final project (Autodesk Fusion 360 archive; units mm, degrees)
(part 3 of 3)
sketch "Sketch40" plane through (0, 0, 61) normal (0, 0, -1) x axis (1, 0, 0)
  line L1 (-2.7532, -2.8573) -> (-0.5532, -2.8573)
  line L2 (-2.7532, -1.0573) -> (-2.7532, -2.8573)
  line L3 (-0.5532, -1.0573) -> (-2.7532, -1.0573)
  line L4 (-0.5532, -2.8573) -> (-0.5532, -1.0573)
  line L5 (-2.7532, 0.4427) -> (-0.5532, 0.4427)
  line L6 (-2.7532, 2.1427) -> (-2.7532, 0.4427)
  line L7 (-0.5532, 2.1427) -> (-2.7532, 2.1427)
  line L8 (-0.5532, 0.4427) -> (-0.5532, 2.1427)
  line L9 (-2.7532, -6.1573) -> (-0.5532, -6.1573)
  line L10 (-2.7532, -4.2573) -> (-2.7532, -6.1573)
  line L11 (-0.5532, -4.2573) -> (-2.7532, -4.2573)
  line L12 (-0.5532, -6.1573) -> (-0.5532, -4.2573)
  line L13 (2.1468, -6.9573) -> (-4.8532, -6.9573)
  line L14 (2.1468, 3.5427) -> (2.1468, -6.9573)
  line L15 (-4.8532, 3.5427) -> (2.1468, 3.5427)
  line L16 (-4.8532, -6.9573) -> (-4.8532, 3.5427)
  circle C1 centre (1, -3) radius 1
  circle C2 centre (-3.6986, -0.074) radius 1
  dimension "d376" diameter C1 = 2
  dimension "d377" diameter C2 = 2
offset_faces "OffsetFaces3" distance -0.3
position "Position24"
work_plane "WorkPlane2" AlongDistance -10
sketch "Sketch46" plane through (0, -46, 0) normal (0, -1, 0) x axis (-1, 0, 0)
  circle C1 centre (-5, 0) radius 2.87
  circle C2 centre (5, 0) radius 2.87
  circle C3 centre (5, 0) radius 3.6
  circle C4 centre (-5, 0) radius 3.6
  concentric C2 C3
  concentric C1 C4
  dimension "d428" diameter C1 = 5.74
  dimension "d429" diameter C2 = 5.74
extrude "Extrude64" add sketch "Sketch46" against normal blind 3
fillet "Fillet21" radius 6
fillet "Fillet22" radius 1.75
extrude "Extrude65" cut of existing geometry blind -2.3
delete_face "DeleteFace3"
delete_face "DeleteFace4"
delete_face "DeleteFace5"
delete_face "DeleteFace6"
chamfer "Chamfer10" distance 1
fillet "Fillet23" radius 1
extrude "Extrude66" cut of existing geometry blind -0.4
extrude "Extrude2" add sketch "Sketch40" profile of C1 C2 along normal blind 2
move "Move2"
combine "Combine12"
move "Move3"
move "Move4"
move "Move1"
move "Move2"
split "Split2"
fillet "Fillet11" radius 2
sketch "Sketch39" plane through (-4.8984, -6.1813, -26.5444) normal (0, 1, 0) x axis (-1, 0, 0)
  curve K1 (9.9684, 4.6149) -> (-9.6449, 8.3119)
  curve K2 (-9.6449, -8.3119) -> (9.9684, -4.6149)
  arc A1 centre (0, 0) radius 12.7324 clockwise from (-9.6449, -8.3119) to (-9.6449, 8.3119)
  arc A2 centre (0, 0) radius 10.9848 clockwise from (9.9684, 4.6149) to (9.9684, -4.6149)
  circle C1 centre (0, 0) radius 3.5
  point P1 (0, 0)
  point P7 (0, 0)
  coincident P1 P7
  dimension "d322" diameter C1 = 7
extrude "Extrude8" cut sketch "Sketch39" profile of C1 against normal blind 9
combine "Combine7"
align "Align1"
fillet "Fillet12" radius 5.75
extrude "Extrude48" sketch "Sketch33" profile of L37 L38 L39 L40 L69 L71 blind -35 from offset 0.5
extrude "Extrude3" sketch "Sketch33" profile of L22 L23 L24 L26 L29 L30 L32 L31 L33 L34 L35 L36 L41 to an object from offset 1
sketch "Sketch1" plane through (0, -41, 0) normal (0, 1, 0) x axis (-1, 0, 0)
  line L1 (21.3009, -9.8876) -> (21.3009, -11.0576)
  line L2 (18.8009, -9.8876) -> (21.3009, -9.8876)
  line L3 (-18.8009, -9.8876) -> (18.8009, -9.8876)
  line L4 (-21.3009, -9.8876) -> (-18.8009, -9.8876)
  line L5 (-21.3009, -9.8876) -> (-21.3009, -11.0576)
  line L6 (-21.3009, -11.0576) -> (-18.8009, -11.0576)
  line L7 (-18.8009, -11.0576) -> (18.8009, -11.0576)
  line L8 (18.8009, -11.0576) -> (21.3009, -11.0576)
  line L9 (8.5, -15.4444) -> (-8.5, -15.4444)
  line L10 (8.5, -22.4444) -> (8.5, -15.4444)
  line L11 (-8.5, -22.4444) -> (8.5, -22.4444)
  line L12 (-8.5, -15.4444) -> (-8.5, -22.4444)
  line L13 (27, 0) -> (25.3, 0)
  line L14 (-25.2982, -0.3) -> (-26.9983, -0.3)
  arc A1 centre (0, 0) radius 25.3 clockwise from (-25.2982, -0.3) to (25.3, 0)
  arc A2 centre (0, 0) radius 24 clockwise from (-23.5661, -4.543) to (23.5661, -4.543)
  arc A3 centre (0, 0) radius 24 clockwise from (23.5661, -4.543) to (-23.5073, -4.838)
  arc A4 centre (0, 0) radius 27 clockwise from (-26.9983, -0.3) to (27, 0)
  point P22 (-8.5, -22.4444)
  point P21 (8.5, -22.4444)
  point P19 (-8.5, -15.4444)
  horizontal L9
  vertical L10
  horizontal L11
  vertical L12
  coincident A3 P22
  coincident A3 P21
  dimension "d333" distance P21 P22 = 17
  dimension "d334" distance P19 P22 = 7
extrude "Extrude1" new body sketch "Sketch1" profile of L9 L10 L11 L12 blind 37 from offset 0.5
combine "Combine5"
offset_faces "OffsetFaces2" distance -0.3
sketch "Sketch41" plane through (-0.0452, -38.1813, 0) normal (0, 1, 0) x axis (-1, 0, 0)
  line L1 (-6.6018, -25.2535) -> (-13, -25.2535)
  line L2 (-6.6018, -28.2535) -> (-6.6018, -25.2535)
  line L3 (-13, -28.2535) -> (-6.6018, -28.2535)
  line L4 (-13, -25.2535) -> (-13, -28.2535)
  line L5 (-6.6018, -28.2535) -> (-13, -25.2535)
  line L6 (-13, -28.2535) -> (-6.6018, -25.2535)
  circle C1 centre (-15.1468, -26.5444) radius 5.35
  point P7 (-9.8009, -26.7535)
  horizontal L1
  perpendicular L1 L2
  parallel L1 L3
  parallel L2 L4
  coincident L5 P7
  coincident L6 P7
  coincident C1 P7
  dimension "d386" distance L1 L3 = 3
extrude "Extrude15" cut sketch "Sketch41" profile of C1 L1 L2 L3 L4 along normal blind 3
sketch "Sketch42" plane through (-0.0452, -38.1813, 0) normal (0, 1, 0) x axis (-1, 0, 0)
  line L1 (17.2217, -25) -> (24, -25)
  line L2 (17.2217, -28.4977) -> (17.2217, -25)
  line L3 (24, -28.4977) -> (17.2217, -28.4977)
  line L4 (24, -25) -> (24, -28.4977)
  line L5 (17.2217, -28.4977) -> (24, -25)
  line L6 (24, -28.4977) -> (17.2217, -25)
  circle C1 centre (24.8532, -26.5444) radius 5.35
  point P7 (20.6109, -26.7489)
  horizontal L1
  perpendicular L1 L2
  parallel L1 L3
  parallel L2 L4
  coincident L5 P7
  coincident L6 P7
extrude "Extrude16" cut sketch "Sketch42" profile of C1 L1 L2 L3 L4 along normal blind 3
offset_faces "OffsetFaces3" distance 1
combine "Combine6"
move "Move3"
move "Move4"
extrude "Extrude54" cut of existing geometry blind -50.1
move "Move5"
offset_faces "OffsetFaces2" distance -0.3
sketch "Sketch43" plane through (0, -56, 0) normal (0, -1, 0) x axis (1, 0, 0)
  line L1 (1, 5.1235) -> (1, -5.1235)
  curve K1 (11.1015, -5.8151) -> (-8.5037, -6.6332)
  curve K2 (-8.5037, 6.6332) -> (11.1015, 5.8151)
  line L2 (-1, -5.1235) -> (-1, 5.1235)
  arc A1 centre (0, 0) radius 9.5 clockwise from (5.8462, 7.4882) to (5.8462, -7.4882)
  arc A2 centre (4, -5.1235) radius 3 clockwise from (5.8462, -7.4882) to (1, -5.1235)
  arc A3 centre (4, 5.1235) radius 3 clockwise from (1, 5.1235) to (5.8462, 7.4882)
  arc A4 centre (0, 0) radius 12.5324 clockwise from (11.1015, 5.8151) to (11.1015, -5.8151)
  arc A5 centre (0, 0) radius 10.7848 clockwise from (-8.5037, -6.6332) to (-8.5037, 6.6332)
  arc A6 centre (-4, -5.1235) radius 3 clockwise from (-1, -5.1235) to (-5.8462, -7.4882)
  arc A7 centre (0, 0) radius 9.5 clockwise from (-5.8462, -7.4882) to (-5.8462, 7.4882)
  arc A8 centre (-4, 5.1235) radius 3 clockwise from (-5.8462, 7.4882) to (-1, 5.1235)
  circle C1 centre (-5, 0) radius 3.5
  circle C2 centre (5.5, 0) radius 3.5
  dimension "d395" diameter C1 = 7
  dimension "d396" diameter C2 = 7
extrude "Extrude55" cut sketch "Sketch43" profile of C1 against normal blind 25
sketch "Sketch44" plane through (0, -56, 0) normal (0, -1, 0) x axis (1, 0, 0)
  line L1 (1, 5.1235) -> (1, -5.1235)
  curve K1 (11.1015, -5.8151) -> (-8.5037, -6.6332)
  curve K2 (-8.5037, 6.6332) -> (11.1015, 5.8151)
  line L2 (-1, -5.1235) -> (-1, 5.1235)
  arc A1 centre (0, 0) radius 9.5 clockwise from (5.8462, 7.4882) to (5.8462, -7.4882)
  arc A2 centre (4, -5.1235) radius 3 clockwise from (5.8462, -7.4882) to (1, -5.1235)
  arc A3 centre (4, 5.1235) radius 3 clockwise from (1, 5.1235) to (5.8462, 7.4882)
  arc A4 centre (0, 0) radius 12.5324 clockwise from (11.1015, 5.8151) to (11.1015, -5.8151)
  arc A5 centre (0, 0) radius 10.7848 clockwise from (-8.5037, -6.6332) to (-8.5037, 6.6332)
  arc A6 centre (-4, -5.1235) radius 3 clockwise from (-1, -5.1235) to (-5.8462, -7.4882)
  arc A7 centre (0, 0) radius 9.5 clockwise from (-5.8462, -7.4882) to (-5.8462, 7.4882)
  arc A8 centre (-4, 5.1235) radius 3 clockwise from (-5.8462, 7.4882) to (-1, 5.1235)
  circle C1 centre (5.5, 0) radius 3.5
  dimension "d399" diameter C1 = 7
extrude "Extrude56" cut sketch "Sketch44" profile of C1 against normal blind 26.89
offset_faces "OffsetFaces23" distance -0.32
extrude "Extrude57" cut sketch "Sketch38" profile of A1 K1 A2 K2 along normal blind 6 bodies "main body (1)"
chamfer "Chamfer1" distance 3
chamfer "Chamfer2" distance 3
extrude "Extrude9" cut of existing geometry blind -1
extrude "Extrude10" cut of existing geometry blind -2
chamfer "Chamfer11" distance 0.5
offset_faces "OffsetFaces27" distance 1.5
offset_faces "OffsetFaces28" distance 0.5
combine "Combine13"
move "Move11"
align "Align1"
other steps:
create_component "CreateComponent3"
create_component "CreateComponent6"
create_component "CreateComponent7"
create_component "CreateComponent8"
create_component "CreateComponent9"
create_component "CreateComponent1"
named bodies: "back cover", "main body", "top cover", "main body (1)"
